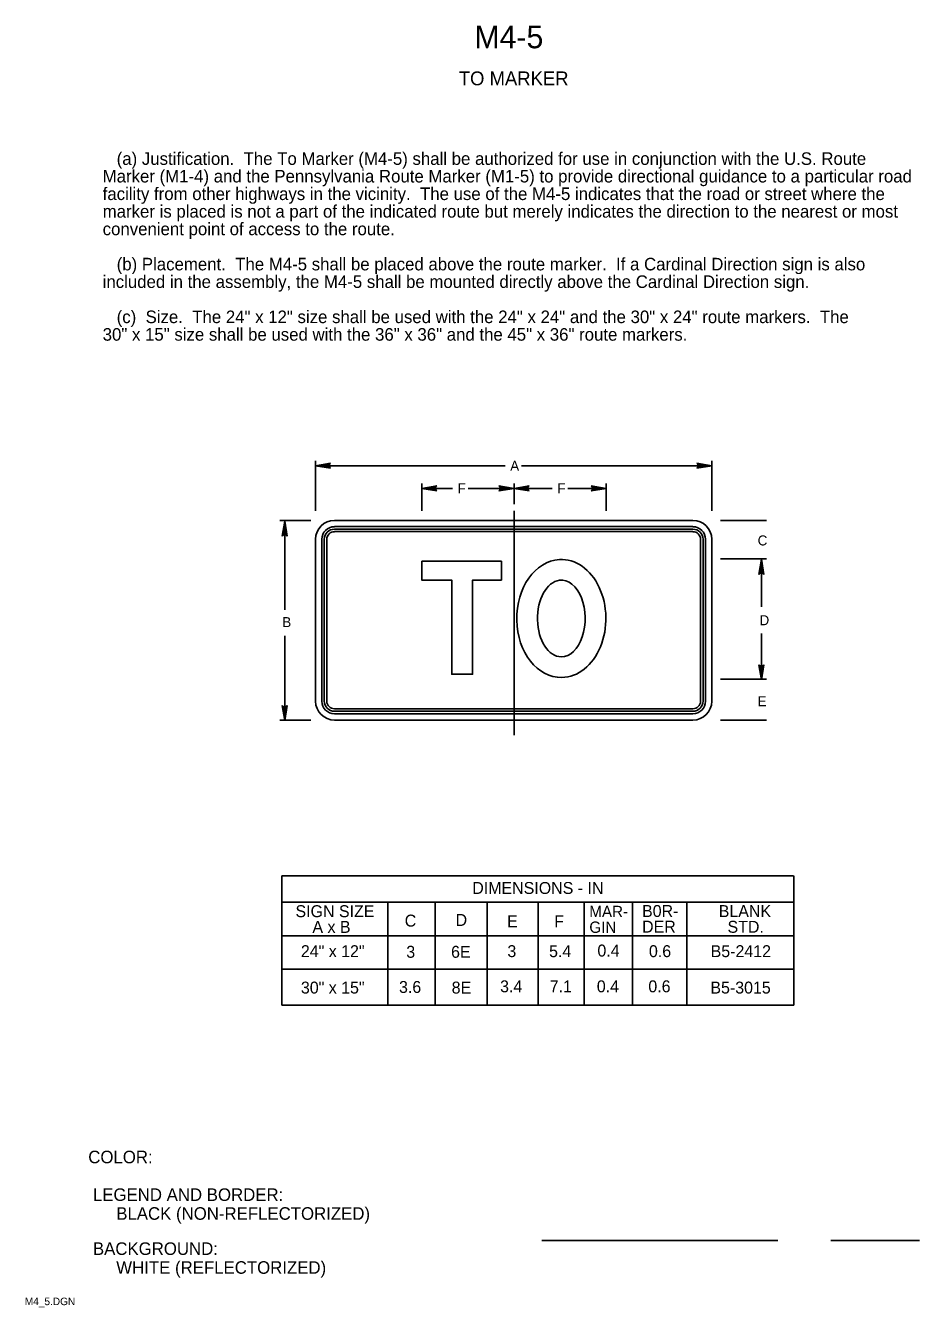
# Model space of a CAD drawing. Extents: x 0.013 to 0.191, y 0.004 to 0.259.
import ezdxf

# ---------------------------------------------------------------- set-up
doc = ezdxf.new("R2010")
doc.units = 0
for name, color, linetype in [('1', 7, 'Continuous'), ('2', 7, 'Continuous'), ('3', 7, 'Continuous')]:
    doc.layers.add(name, color=color, linetype=linetype)

# ---------------------------------------------------------------- blocks, each defined once
blk = doc.blocks.new('RARROW')
at = {"layer": '3'}
for p, q in [((-2.156, 0.285), (-2.2665, 0.384625)), ((-2.2665, 0.384625), (0, 0)), ((0, 0), (-2.2665, -0.379125)), ((-2.156, 0.285), (-2.075625, 0.12075)), ((0, 0), (-2.156, 0.285)), ((-2.14975, -0.2705), (0, 0)), ((-2.075625, 0.12075), (0, 0)), ((0, 0), (-2.074, -0.108)), ((-2.2665, -0.379125), (-2.14975, -0.2705)), ((-2.074, -0.108), (-2.14975, -0.2705))]:
    blk.add_line(p, q, dxfattribs=at)

msp = doc.modelspace()

# ---------------------------------------------------------------- linework, layer by layer
at = {"layer": '1'}
for p, q in [((0.11544, 0.01723), (0.16242, 0.01723)), ((0.17295, 0.01723), (0.19056, 0.01723))]:
    msp.add_line(p, q, dxfattribs=at)
at = {"layer": '3'}
for p, q in [((0.07038, 0.16255), (0.07038, 0.1725)), ((0.10812, 0.1715), (0.07038, 0.1715)), ((0.11138, 0.1715), (0.14925, 0.1715)), ((0.14925, 0.16255), (0.14925, 0.1725)), ((0.0915, 0.16255), (0.0915, 0.168)), ((0.09763, 0.167), (0.0915, 0.167)), ((0.10075, 0.167), (0.10988, 0.167)), ((0.10988, 0.16387), (0.10988, 0.168)), ((0.1175, 0.167), (0.10988, 0.167)), ((0.12062, 0.167), (0.12825, 0.167)), ((0.12825, 0.16255), (0.12825, 0.168)), ((0.10988, 0.1625), (0.10988, 0.11788)), ((0.06942, 0.16062), (0.06329, 0.16062)), ((0.06429, 0.14282), (0.06429, 0.16062)), ((0.07412, 0.16062), (0.1455, 0.16062)), ((0.07412, 0.15938), (0.1455, 0.15938)), ((0.07412, 0.15888), (0.1455, 0.15888)), ((0.07412, 0.15838), (0.1455, 0.15838)), ((0.151, 0.16062), (0.16012, 0.16062)), ((0.07038, 0.12462), (0.07038, 0.15687)), ((0.07163, 0.12462), (0.07163, 0.15687)), ((0.07212, 0.12462), (0.07212, 0.15687)), ((0.07262, 0.12462), (0.07262, 0.15687)), ((0.147, 0.15687), (0.147, 0.12462)), ((0.1475, 0.15687), (0.1475, 0.12462)), ((0.148, 0.15687), (0.148, 0.12462)), ((0.14925, 0.15687), (0.14925, 0.12462)), ((0.151, 0.153), (0.16012, 0.153)), ((0.15913, 0.149), (0.15913, 0.153)), ((0.15913, 0.14338), (0.15913, 0.153)), ((0.15913, 0.13812), (0.15913, 0.129)), ((0.06429, 0.13762), (0.06429, 0.12087)), ((0.15913, 0.133), (0.15913, 0.129)), ((0.151, 0.129), (0.16012, 0.129)), ((0.1455, 0.12312), (0.07412, 0.12312)), ((0.1455, 0.12262), (0.07412, 0.12262)), ((0.06942, 0.12087), (0.06329, 0.12087)), ((0.1455, 0.12212), (0.07412, 0.12212)), ((0.1455, 0.12087), (0.07412, 0.12087)), ((0.151, 0.12087), (0.16012, 0.12087)), ((0.06363, 0.08987), (0.1655, 0.08987)), ((0.06367, 0.08987), (0.06367, 0.06414)), ((0.16555, 0.08987), (0.16555, 0.06414)), ((0.16555, 0.08461), (0.06363, 0.08461)), ((0.08477, 0.08461), (0.08477, 0.06414)), ((0.09418, 0.08461), (0.09418, 0.06414)), ((0.10456, 0.08461), (0.10456, 0.06414)), ((0.1147, 0.08461), (0.1147, 0.06414)), ((0.12383, 0.08461), (0.12383, 0.06414)), ((0.13346, 0.08461), (0.13346, 0.06414)), ((0.1443, 0.08461), (0.1443, 0.06414)), ((0.06363, 0.07792), (0.16555, 0.07792)), ((0.06364, 0.07129), (0.16556, 0.07129)), ((0.06363, 0.06414), (0.16555, 0.06414))]:
    msp.add_line(p, q, dxfattribs=at)
msp.add_lwpolyline([(0.0915, 0.1525), (0.10737, 0.1525), (0.10737, 0.14875), (0.10163, 0.14875), (0.10163, 0.13), (0.0975, 0.13), (0.0975, 0.14875), (0.0915, 0.14875), (0.0915, 0.1525)], dxfattribs=at)
for centre, radius, start, end in [((0.07412, 0.15687), 0.00375, 90, 180), ((0.07412, 0.15687), 0.0025, 90, 180), ((0.07412, 0.15687), 0.002, 90, 180), ((0.07412, 0.15687), 0.0015, 90, 180), ((0.1455, 0.15687), 0.00375, 0, 90), ((0.1455, 0.15687), 0.0025, 0, 90), ((0.1455, 0.15687), 0.002, 0, 90), ((0.1455, 0.15687), 0.0015, 0, 90), ((0.07415, 0.12464), 0.00377, 180.294, 270.294), ((0.07412, 0.12462), 0.0025, 180, 270), ((0.07412, 0.12462), 0.002, 180, 270), ((0.07412, 0.12462), 0.0015, 180, 270), ((0.1455, 0.12462), 0.00375, 270, 0), ((0.1455, 0.12462), 0.0025, 270, 0), ((0.1455, 0.12462), 0.002, 270, 0), ((0.1455, 0.12462), 0.0015, 270, 0)]:
    msp.add_arc(centre, radius, start, end, dxfattribs=at)
for major_axis, ratio, start_param, end_param in [((0, -0.01175), 0.755319, 3.182942, 6.296845), ((0, -0.01175), 0.755319, 0.013648, 3.183761), ((0, -0.00762), 0.622951, 3.215547, 6.284119), ((0, -0.00762), 0.622951, 0.000933, 3.21373)]:
    msp.add_ellipse((0.11929, 0.14109), major_axis=major_axis, ratio=ratio, start_param=start_param, end_param=end_param, dxfattribs=at)

# ---------------------------------------------------------------- block references
at = {"layer": '3', "xscale": 0.0013236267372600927, "yscale": 0.001309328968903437}
for p, rotation in [((0.07038, 0.1715), 180), ((0.0915, 0.167), 180), ((0.10988, 0.167), 180), ((0.06425, 0.1605), 90), ((0.15913, 0.15288), 90), ((0.15913, 0.12887), -90), ((0.06425, 0.12075), -90)]:
    msp.add_blockref('RARROW', p, dxfattribs=dict(at, rotation=rotation))
for p in [(0.14925, 0.1715), (0.10988, 0.167), (0.12825, 0.167)]:
    msp.add_blockref('RARROW', p, dxfattribs=at)

# ---------------------------------------------------------------- texts
at = {"layer": '1'}
for s, height, p in [('M4-5', 0.0045, (0.102, 0.25462)), ('TO MARKER', 0.00275, (0.09888, 0.24725)), ('COLOR:', 0.0025, (0.02513, 0.03263)), (' LEGEND AND BORDER:', 0.0024998, (0.02513, 0.02513)), ('      BLACK (NON-REFLECTORIZED)', 0.0024998, (0.02513, 0.02138)), (' BACKGROUND:', 0.0024998, (0.02513, 0.01438)), ('      WHITE (REFLECTORIZED)', 0.0024998, (0.02513, 0.01063)), ('M4_5.DGN', 0.0015, (0.0125, 0.00438))]:
    msp.add_text(s, height=height, dxfattribs=at).set_placement(p)
at = {"layer": '2'}
for s, height, p in [('   (a) Justification.  The To Marker (M4-5) shall be authorized for use in conjunction with the U.S. Route ', 0.00249975, (0.028, 0.2314)), ('Marker (M1-4) and the Pennsylvania Route Marker (M1-5) to provide directional guidance to a particular road ', 0.00249975, (0.028, 0.2279)), ('facility from other highways in the vicinity.  The use of the M4-5 indicates that the road or street where the ', 0.00249975, (0.028, 0.2244)), ('marker is placed is not a part of the indicated route but merely indicates the direction to the nearest or most ', 0.00249975, (0.028, 0.2209)), ('convenient point of access to the route.', 0.0024998, (0.028, 0.2174)), ('   (b) Placement.  The M4-5 shall be placed above the route marker.  If a Cardinal Direction sign is also', 0.00249975, (0.028, 0.2104)), ('included in the assembly, the M4-5 shall be mounted directly above the Cardinal Direction sign.', 0.0024998, (0.028, 0.2069)), ('   (c)  Size.  The 24" x 12" size shall be used with the 24" x 24" and the 30" x 24" route markers.  The', 0.00249975, (0.028, 0.1999)), ('30" x 15" size shall be used with the 36" x 36" and the 45" x 36" route markers.', 0.0024998, (0.028, 0.1964))]:
    msp.add_text(s, height=height, dxfattribs=at).set_placement(p)
at = {"layer": '3'}
for s, height, p in [('A', 0.002, (0.10912, 0.1705)), ('F', 0.002, (0.09863, 0.166)), ('F', 0.002, (0.1185, 0.166)), ('C', 0.002, (0.15838, 0.15563)), ('B', 0.002, (0.06375, 0.13937)), ('D', 0.002, (0.15875, 0.13975)), ('E', 0.002, (0.15838, 0.12362)), ('DIMENSIONS - IN', 0.0023752, (0.10157, 0.08625)), ('SIGN SIZE', 0.002375, (0.06638, 0.08163)), ('C', 0.00238, (0.08812, 0.07975)), ('D', 0.00238, (0.09825, 0.07988)), ('E', 0.00238, (0.1085, 0.07963)), ('F', 0.00238, (0.11788, 0.07963)), ('MAR-', 0.002257, (0.12487, 0.08163)), ('B0R-', 0.002375, (0.13537, 0.08167)), ('BLANK', 0.002375, (0.15063, 0.08165)), ('A x B', 0.002375, (0.06975, 0.0785)), ('GIN', 0.002257, (0.12487, 0.0785)), ('DER', 0.002375, (0.13537, 0.07855)), ('STD.', 0.002375, (0.15238, 0.07852)), ('24" x 12"', 0.002375, (0.06746, 0.07367)), ('3', 0.00238, (0.08843, 0.07354)), ('6E', 0.002375, (0.09735, 0.07354)), ('3', 0.00238, (0.10856, 0.07367)), ('5.4', 0.002375, (0.11686, 0.07367)), ('0.4', 0.002375, (0.12648, 0.07379)), ('0.6', 0.002375, (0.13674, 0.07367)), ('B5-2412', 0.002375, (0.14902, 0.07367)), ('3.6', 0.002375, (0.08699, 0.06654)), ('3.4', 0.002375, (0.10711, 0.06667)), ('7.1', 0.002375, (0.11699, 0.06667)), ('0.4', 0.002375, (0.12636, 0.06667)), ('0.6', 0.002375, (0.13662, 0.06667)), ('30" x 15"', 0.002375, (0.06746, 0.06642)), ('8E', 0.002375, (0.09747, 0.06642)), ('B5-3015', 0.002375, (0.14897, 0.06642))]:
    msp.add_text(s, height=height, dxfattribs=at).set_placement(p)

doc.saveas('drawing.dxf')
